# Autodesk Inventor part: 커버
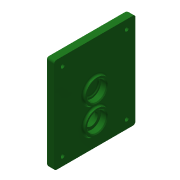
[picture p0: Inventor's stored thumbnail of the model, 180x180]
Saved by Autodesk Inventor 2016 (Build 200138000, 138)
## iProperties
Created: 2016-02
Part Number: 커버
Material: 알루미늄 6061
Document SubType Name: Modeling
Designer: mduedu
Density: 2.71 g/cm^3
Appearance: 매끄러움 - 짙은 산림 녹색
Mass: 272.254 g
Surface Area: 266.629 cm^2
Volume: 100.463 cm^3
Author: mduedu
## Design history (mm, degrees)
sketch "스케치1"
  geometry: L1 (63, 47)-(-47, 47); L2 (-47, 47)-(-47, -47); L3 (-47, -47)-(63, -47); L4 (63, -47)-(63, 47); 2 further points
  constraints: 8 end point, 2 parallel, 1 horizontal, 1 horizontal alignment, 1 midpoint, 1 perpendicular
  dimensions: "d102" = 94 distance of L3.end L1.start; "d104" = 47 distance from line of L2 point (0, 0); "d105" = 110 distance of L1.start L1.end
extrude "돌출1" new body sketch "스케치1" distance "d1" = 10; taper "d2" = 0 deg
sketch "스케치2"
  geometry: C1 r 14 at (0, 11); 1 further point
  constraints: 1 centre point, 1 vertical alignment
  dimensions: "d3" = 28 diameter of C1; "d6" = 11 distance of C1.centre point (0, 0)
extrude "돌출2" join sketch "스케치2" distance "d7" = 3; taper "d8" = 0 deg
sketch "스케치3"
  geometry: C1 r 14 at (0, -20); 1 further point
  constraints: 1 centre point, 1 vertical alignment
  dimensions: "d9" = 28 diameter of C1; "d10" = 20 distance of C1.centre point (0, 0)
extrude "돌출3" join sketch "스케치3" distance "d11" = 3; taper "d12" = 0 deg
hole "구멍1" diameter "d15" = 22; stored, may be unused: countersink angle "d19" = 90 deg, drill point angle "d21" = 0 deg; dims "d13" = 10, "d14" = 10, "d16" = 6, "d17" = 4, "d18" = 2, "d20" = 7
hole "구멍2" diameter "d24" = 18; stored, may be unused: countersink angle "d28" = 90 deg, drill point angle "d30" = 0 deg; dims "d22" = 10, "d23" = 10, "d25" = 6, "d26" = 4, "d27" = 2, "d29" = 1
hole "구멍3" diameter "d33" = 22; stored, may be unused: countersink angle "d37" = 90 deg, drill point angle "d39" = 0 deg; dims "d34" = 6, "d35" = 4, "d36" = 2, "d38" = 7, "d73" = 10, "d74" = 10
sketch "스케치4"
  geometry: C1 r 14 at (0, -20) reference; C2 r 18 at (0, -20); 1 further point
  constraints: 1 centre point, 1 coincident
  dimensions: "d40" = 36 diameter of C2
extrude "돌출4" join sketch "스케치4" distance "d41" = 4; taper "d42" = 0 deg
hole "구멍4" diameter "d45" = 22; stored, may be unused: countersink angle "d49" = 90 deg, drill point angle "d51" = 0 deg; dims "d43" = 10, "d44" = 10, "d46" = 6, "d47" = 4, "d48" = 2, "d50" = 7
hole "구멍5" diameter "d54" = 15; stored, may be unused: countersink angle "d58" = 90 deg, drill point angle "d60" = 0 deg; dims "d52" = 10, "d53" = 10, "d55" = 6, "d56" = 4, "d57" = 2, "d59" = 7
fillet "모깎기1" dims "d61" = 0.3
fillet "모깎기2" dims "d62" = 2
chamfer "모따기1" distance "d63" = 1; stored, may be unused: second distance "d64" = 2, angle "d65" = 45 deg
fillet "모깎기6" dims "d88" = 2
fillet "모깎기4" dims "d75" = 2
sketch "스케치9"
  geometry: L1 (47, 63)-(47, -47) reference; L2 (-47, 63)-(47, 63) reference; L3 (-47, -47)-(-47, 63) reference; L4 (47, -47)-(-47, -47) reference; L5 (37, 53)-(37, -37); L6 (37, -37)-(-37, -37); L7 (-37, -37)-(-37, 53); L8 (-37, 53)-(37, 53); C1 r 20 at (0, -20) reference; 5 further points
  constraints: 8 end point, 4 coincident, 3 other
  dimensions: "d107" = 10 distance between parallel lines of L8 L2
hole "구멍7" sketch "스케치9" at (-37, 53), (37, 53), (37, -37), (-37, -37) diameter "d108" = 4.5; stored, may be unused: countersink angle "d112" = 90 deg, drill point angle "d114" = 118 deg; dims "d109" = 6, "d110" = 8, "d111" = 4.6, "d113" = 8
fillet "모깎기8" dims "d106" = 3
fillet "모깎기9" dims "d115" = 3
node "솔리드1"
node "투영된 루프2"
